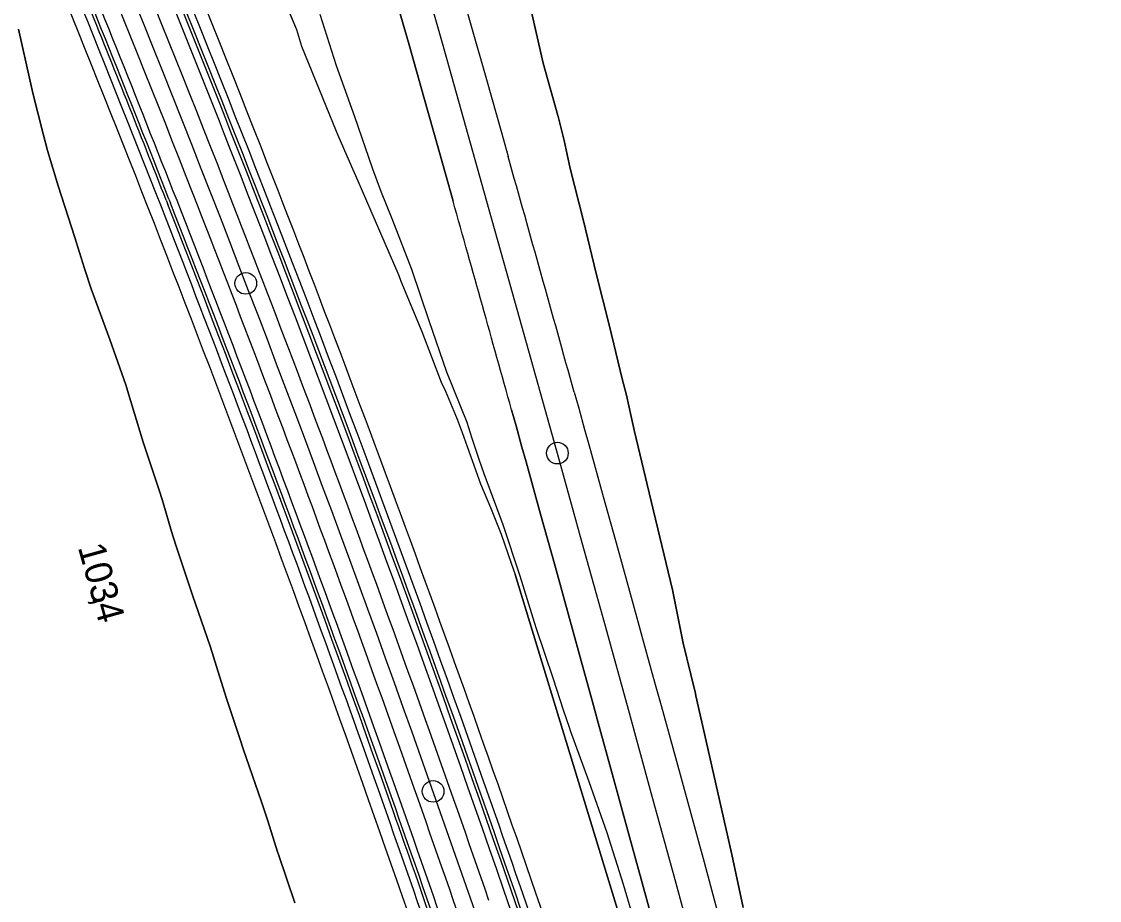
# Model space of a CAD drawing. Extents: x -678487 to -674601, y -1104811 to -1093295.
# Drawn here: x -676319.1 to -676120.1, y -1100094.2 to -1099931.9 of the extents above; entities that cross this region are included whole.
import ezdxf

# ---------------------------------------------------------------- set-up
doc = ezdxf.new("R2010")
doc.units = 0
for name, color, linetype in [('00_MiNGO', 7, 'Continuous'), ('SOxx02xx_Staničení_Popis', 7, 'Continuous'), ('SOxx02xx_ŽSp_hrana', 7, 'Continuous'), ('SOxx02xx_ŽSp_odvodnění', 7, 'Continuous'), ('SOxx02xx_ŽSp_zářez_hrana', 7, 'Continuous'), ('SOxx02xx_ŽSp_zářez_plocha', 7, 'Continuous'), ('SOxxxxxx_Osa_bod_P', 7, 'Continuous'), ('SOxxxxxx_Staničení_Popis', 7, 'Continuous'), ('SOxxxxxx_ŽSp_hrana', 7, 'Continuous'), ('SOxxxxxx_ŽSp_násyp_hrana', 7, 'Continuous'), ('SOxxxxxx_ŽSp_násyp_plocha', 7, 'Continuous')]:
    doc.layers.add(name, color=color, linetype=linetype)

msp = doc.modelspace()

# ---------------------------------------------------------------- linework, layer by layer
at = {"layer": '00_MiNGO'}
msp.add_line((-676192.76, -1100149.21), (-676227.95, -1100033.98), dxfattribs=at)
at = {"layer": 'SOxx02xx_Staničení_Popis'}
for centre in [(-676277.7, -1099980.23), (-676243.11, -1100074.06)]:
    msp.add_circle(centre, 2, dxfattribs=at)
at = {"layer": 'SOxx02xx_ŽSp_hrana'}
for centre, radius, start, end in [((-679543.77, -1101237.56), 3502.82, 21.366, 23.18091), ((-679544.28, -1101237.79), 3497.18, 21.36502, 23.18061), ((-679543.77, -1101237.56), 3502.82, 19.05102, 21.366), ((-679544.28, -1101237.79), 3497.18, 19.04918, 21.36502)]:
    msp.add_arc(centre, radius, start, end, dxfattribs=at)
at = {"layer": 'SOxx02xx_ŽSp_odvodnění'}
for p, q in [((-676292.41, -1099964.87), (-676292.11, -1099965.64)), ((-676291.9, -1099964.67), (-676291.6, -1099965.43))]:
    msp.add_line(p, q, dxfattribs=at)
for centre, radius, start, end in [((-679543.35, -1101237.38), 3507.42, 21.3668, 23.18116), ((-679543.4, -1101237.4), 3506.91, 21.36671, 22.7556), ((-679544.65, -1101237.95), 3493.09, 21.37783, 22.36101), ((-679544.7, -1101237.97), 3492.59, 21.37774, 22.02868), ((-679543.4, -1101237.4), 3506.92, 17.20156, 21.36671), ((-679543.35, -1101237.38), 3507.42, 18.2706, 21.3668), ((-679544.7, -1101237.97), 3492.59, 19.40341, 21.36421), ((-679544.65, -1101237.95), 3493.09, 19.04784, 21.3643), ((-679544.7, -1101237.97), 3492.59, 18.59256, 19.40341)]:
    msp.add_arc(centre, radius, start, end, dxfattribs=at)
at = {"layer": 'SOxx02xx_ŽSp_zářez_hrana'}
for p, q in [((-676271.23, -1099926.44), (-676268.36, -1099933.36)), ((-676319.71, -1099933.27), (-676317.54, -1099942.86)), ((-676268.36, -1099933.36), (-676267.4, -1099936.4)), ((-676267.4, -1099936.4), (-676264.86, -1099942.79)), ((-676317.54, -1099942.86), (-676316.95, -1099945.36)), ((-676264.86, -1099942.79), (-676261.03, -1099952.09)), ((-676316.95, -1099945.36), (-676315.12, -1099952.63)), ((-676261.03, -1099952.09), (-676260.71, -1099952.86)), ((-676315.12, -1099952.63), (-676314.3, -1099955.7)), ((-676260.71, -1099952.86), (-676258.64, -1099957.69)), ((-676314.3, -1099955.7), (-676312.33, -1099962.24)), ((-676258.64, -1099957.69), (-676256.99, -1099961.3)), ((-676256.99, -1099961.3), (-676252.99, -1099970.53)), ((-676312.33, -1099962.24), (-676309.28, -1099971.75)), ((-676309.28, -1099971.75), (-676309.03, -1099972.53)), ((-676252.99, -1099970.53), (-676249.42, -1099978.78)), ((-676309.03, -1099972.53), (-676307.47, -1099977.51)), ((-676307.47, -1099977.51), (-676306.26, -1099981.26)), ((-676249.42, -1099978.78), (-676249.09, -1099979.8)), ((-676249.09, -1099979.8), (-676245.22, -1099989.09)), ((-676306.26, -1099981.26), (-676302.83, -1099990.61)), ((-676245.22, -1099989.09), (-676241.62, -1099998.48)), ((-676302.83, -1099990.61), (-676299.88, -1099999)), ((-676299.88, -1099999), (-676299.83, -1099999.16)), ((-676299.83, -1099999.16), (-676299.55, -1100000.01)), ((-676299.55, -1100000.01), (-676296.69, -1100009.58)), ((-676241.62, -1099998.48), (-676240.85, -1100000.15)), ((-676240.85, -1100000.15), (-676238.69, -1100005.3)), ((-676238.69, -1100005.3), (-676237.73, -1100007.76)), ((-676237.73, -1100007.76), (-676234.34, -1100017.23)), ((-676296.69, -1100009.58), (-676293.49, -1100019.01)), ((-676234.34, -1100017.23), (-676232.52, -1100021.61)), ((-676293.49, -1100019.01), (-676292.97, -1100020.76)), ((-676292.97, -1100020.76), (-676291.43, -1100026.09)), ((-676232.52, -1100021.61), (-676230.57, -1100026.55)), ((-676291.43, -1100026.09), (-676290.65, -1100028.58)), ((-676230.57, -1100026.55), (-676228.69, -1100031.93)), ((-676290.65, -1100028.58), (-676287.49, -1100038.02)), ((-676228.69, -1100031.93), (-676227.95, -1100033.98)), ((-676287.49, -1100038.02), (-676285.94, -1100042.45)), ((-676285.94, -1100042.45), (-676284.25, -1100047.43)), ((-676284.25, -1100047.43), (-676282.56, -1100052.81)), ((-676282.56, -1100052.81), (-676281.25, -1100056.93)), ((-676281.25, -1100056.93), (-676278.89, -1100064.12)), ((-676278.89, -1100064.12), (-676278.13, -1100066.38)), ((-676278.13, -1100066.38), (-676274.88, -1100075.78)), ((-676274.88, -1100075.78), (-676273.64, -1100079.49)), ((-676273.64, -1100079.49), (-676271.83, -1100085.25)), ((-676271.83, -1100085.25), (-676271.68, -1100085.72)), ((-676271.68, -1100085.72), (-676268.64, -1100094.67))]:
    msp.add_line(p, q, dxfattribs=at)
for centre, radius, start, end in [((-679543.25, -1101237.33), 3508.58, 21.367, 23.18123), ((-679543.06, -1101237.24), 3510.69, 21.36737, 23.18134), ((-679544.8, -1101238.02), 3491.42, 21.36401, 22.85251), ((-679543.5, -1101237.44), 3505.75, 21.36651, 22.7555), ((-679544.54, -1101237.91), 3494.25, 21.36451, 22.36114), ((-679544.99, -1101238.11), 3489.31, 19.0466, 22.3606), ((-679543.06, -1101237.24), 3510.69, 18.59094, 21.36737), ((-679543.5, -1101237.44), 3505.75, 17.15913, 21.36651), ((-679543.25, -1101237.33), 3508.58, 19.41645, 21.367), ((-679544.8, -1101238.02), 3491.42, 19.04729, 21.36401), ((-679544.54, -1101237.91), 3494.25, 19.04822, 21.36451), ((-679543.25, -1101237.33), 3508.58, 19.03362, 19.41645), ((-679543.25, -1101237.33), 3508.58, 17.16041, 19.03362)]:
    msp.add_arc(centre, radius, start, end, dxfattribs=at)
at = {"layer": 'SOxx02xx_ŽSp_zářez_plocha'}
msp.add_line((-676227.95, -1100033.98), (-676192.76, -1100149.21), dxfattribs=at)
for points in [[(-676271.23, -1099926.44), (-676268.36, -1099933.36), (-676267.4, -1099936.4), (-676264.86, -1099942.79), (-676261.03, -1099952.09), (-676260.71, -1099952.86), (-676258.64, -1099957.69), (-676256.99, -1099961.3), (-676252.99, -1099970.53), (-676249.42, -1099978.78), (-676249.09, -1099979.8), (-676245.22, -1099989.09), (-676241.62, -1099998.48), (-676240.85, -1100000.15), (-676238.69, -1100005.3), (-676237.73, -1100007.76), (-676234.34, -1100017.23), (-676232.52, -1100021.61), (-676230.57, -1100026.55), (-676228.69, -1100031.93), (-676227.95, -1100033.98)], [(-676268.64, -1100094.67), (-676271.68, -1100085.72), (-676271.83, -1100085.25), (-676273.64, -1100079.49), (-676274.88, -1100075.78), (-676278.13, -1100066.38), (-676278.89, -1100064.12), (-676281.25, -1100056.93), (-676282.56, -1100052.81), (-676284.25, -1100047.43), (-676285.94, -1100042.45), (-676287.49, -1100038.02), (-676290.65, -1100028.58), (-676291.43, -1100026.09), (-676292.97, -1100020.76), (-676293.49, -1100019.01), (-676296.69, -1100009.58), (-676299.55, -1100000.01), (-676299.83, -1099999.16), (-676299.88, -1099999), (-676302.83, -1099990.61), (-676306.26, -1099981.26), (-676307.47, -1099977.51), (-676309.03, -1099972.53), (-676309.28, -1099971.75), (-676312.33, -1099962.24), (-676314.3, -1099955.7), (-676315.12, -1099952.63), (-676316.95, -1099945.36), (-676317.54, -1099942.86), (-676319.71, -1099933.27)]]:
    msp.add_lwpolyline(points, dxfattribs=at)
for centre, radius, start, end in [((-679543.06, -1101237.24), 3510.69, 21.36737, 23.18134), ((-679544.99, -1101238.11), 3489.31, 19.0466, 22.3606), ((-679543.06, -1101237.24), 3510.69, 18.59094, 21.36737)]:
    msp.add_arc(centre, radius, start, end, dxfattribs=at)
at = {"layer": 'SOxxxxxx_Osa_bod_P'}
for centre, radius, start, end in [((-693563.22, -1104838.51), 18002.25, 14.227837, 20.731742), ((-679544.02, -1101237.67), 3500, 17.15654, 27.27761)]:
    msp.add_arc(centre, radius, start, end, dxfattribs=at)
at = {"layer": 'SOxxxxxx_Staničení_Popis'}
for p, q in [((-676277.7, -1099980.23), (-676277.7, -1099980.23)), ((-676220.16, -1100011.59), (-676220.16, -1100011.59)), ((-676243.11, -1100074.06), (-676243.11, -1100074.06))]:
    msp.add_line(p, q, dxfattribs=at)
for centre in [(-676277.7, -1099980.23), (-676220.16, -1100011.59), (-676243.11, -1100074.06)]:
    msp.add_circle(centre, 2, dxfattribs=at)
at = {"layer": 'SOxxxxxx_ŽSp_hrana'}
for points in [[(-676289.01, -1099792.09), (-676286.21, -1099801.69), (-676285.8, -1099803.08), (-676284.09, -1099808.96), (-676283.41, -1099811.29), (-676280.62, -1099820.89), (-676277.84, -1099830.49), (-676275.06, -1099840.09), (-676272.29, -1099849.7), (-676271.08, -1099853.88), (-676269.52, -1099859.3), (-676266.75, -1099868.91), (-676264, -1099878.52), (-676261.24, -1099888.13), (-676258.5, -1099897.74), (-676256.5, -1099904.73), (-676255.11, -1099909.63), (-676253.02, -1099916.97), (-676250.29, -1099926.58), (-676247.56, -1099936.2), (-676244.84, -1099945.82), (-676242.08, -1099955.61), (-676240.83, -1099960.03), (-676239.42, -1099965.06)], [(-676238.72, -1099923.3), (-676236, -1099932.93), (-676233.27, -1099942.55), (-676230.51, -1099952.35), (-676229.26, -1099956.77)], [(-676217.05, -1100000.34), (-676216.22, -1100003.31), (-676215.13, -1100007.25), (-676214.37, -1100009.98), (-676211.69, -1100019.61), (-676209.01, -1100029.25), (-676206.34, -1100038.89), (-676203.68, -1100048.54), (-676202.09, -1100054.31), (-676201.02, -1100058.18), (-676198.37, -1100067.82), (-676195.72, -1100077.47), (-676193.08, -1100087.12), (-676190.44, -1100096.77), (-676188.1, -1100105.36), (-676187.3, -1100108.32), (-676185.19, -1100116.07)], [(-676228.63, -1100003.57), (-676227.8, -1100006.54), (-676226.71, -1100010.47), (-676225.95, -1100013.2), (-676223.27, -1100022.83), (-676220.6, -1100032.46), (-676217.93, -1100042.1), (-676215.27, -1100051.73), (-676213.68, -1100057.51), (-676212.61, -1100061.37), (-676209.96, -1100071.01), (-676207.32, -1100080.65), (-676204.68, -1100090.29), (-676202.04, -1100099.93)]]:
    msp.add_lwpolyline(points, dxfattribs=at)
for radius, end in [(18008.26, 15.728738), (17996.24, 15.712091)]:
    msp.add_arc((-693563.22, -1104838.51), radius, 15.584783, end, dxfattribs=at)
at = {"layer": 'SOxxxxxx_ŽSp_násyp_hrana'}
for p, q in [((-676225, -1099929.82), (-676222.8, -1099939.59)), ((-676264.01, -1099930.48), (-676260.99, -1099940)), ((-676260.99, -1099940), (-676257.66, -1099949.44)), ((-676222.8, -1099939.59), (-676220.07, -1099949.22)), ((-676257.66, -1099949.44), (-676254.37, -1099958.89)), ((-676220.07, -1099949.22), (-676220.03, -1099949.39)), ((-676220.03, -1099949.39), (-676218.9, -1099953.85)), ((-676218.9, -1099953.85), (-676217.83, -1099958.99)), ((-676254.37, -1099958.89), (-676254.31, -1099959.06)), ((-676254.31, -1099959.06), (-676252.68, -1099963.37)), ((-676217.83, -1099958.99), (-676215.31, -1099968.68)), ((-676252.68, -1099963.37), (-676250.76, -1099968.25)), ((-676250.76, -1099968.25), (-676247.13, -1099977.61)), ((-676215.31, -1099968.68), (-676212.97, -1099978.42)), ((-676247.13, -1099977.61), (-676243.92, -1099987.09)), ((-676212.97, -1099978.42), (-676210.51, -1099988.12)), ((-676243.92, -1099987.09), (-676240.64, -1099996.55)), ((-676210.51, -1099988.12), (-676208.18, -1099997.87)), ((-676240.64, -1099996.55), (-676236.91, -1100005.88)), ((-676208.18, -1099997.87), (-676207.41, -1100000.85)), ((-676207.41, -1100000.85), (-676206.51, -1100004.85)), ((-676236.91, -1100005.88), (-676235.95, -1100008.81)), ((-676206.51, -1100004.85), (-676205.91, -1100007.62)), ((-676205.91, -1100007.62), (-676203.56, -1100017.36)), ((-676235.95, -1100008.81), (-676234.65, -1100012.68)), ((-676234.65, -1100012.68), (-676233.73, -1100015.37)), ((-676233.73, -1100015.37), (-676230.23, -1100024.76)), ((-676203.56, -1100017.36), (-676201.23, -1100027.09)), ((-676230.23, -1100024.76), (-676227.08, -1100034.26)), ((-676201.23, -1100027.09), (-676198.87, -1100036.83)), ((-676227.08, -1100034.26), (-676224.16, -1100043.82)), ((-676198.87, -1100036.83), (-676196.93, -1100046.67)), ((-676224.16, -1100043.82), (-676220.91, -1100053.29)), ((-676196.93, -1100046.67), (-676195.5, -1100052.5)), ((-676220.91, -1100053.29), (-676219.08, -1100059)), ((-676195.5, -1100052.5), (-676194.67, -1100055.98)), ((-676194.67, -1100055.98), (-676194.58, -1100056.41)), ((-676194.58, -1100056.41), (-676192.36, -1100066.17)), ((-676219.08, -1100059), (-676217.95, -1100062.39)), ((-676217.95, -1100062.39), (-676217.81, -1100062.8)), ((-676217.81, -1100062.8), (-676214.35, -1100072.22)), ((-676192.36, -1100066.17), (-676190.14, -1100075.94)), ((-676214.35, -1100072.22), (-676211.03, -1100081.67)), ((-676190.14, -1100075.94), (-676187.95, -1100085.72)), ((-676211.03, -1100081.67), (-676208.02, -1100091.21)), ((-676187.95, -1100085.72), (-676185.84, -1100095.51)), ((-676208.02, -1100091.21), (-676205.17, -1100100.79))]:
    msp.add_line(p, q, dxfattribs=at)
at = {"layer": 'SOxxxxxx_ŽSp_násyp_plocha'}
for points in [[(-676239.42, -1099965.06), (-676240.83, -1099960.03), (-676242.08, -1099955.61), (-676244.84, -1099945.82), (-676247.56, -1099936.2), (-676250.29, -1099926.58), (-676253.02, -1099916.97), (-676255.11, -1099909.63), (-676256.5, -1099904.73), (-676258.5, -1099897.74), (-676261.24, -1099888.13), (-676264, -1099878.52), (-676266.75, -1099868.91), (-676269.52, -1099859.3), (-676271.08, -1099853.88), (-676272.29, -1099849.7), (-676275.06, -1099840.09), (-676277.84, -1099830.49), (-676280.62, -1099820.89), (-676283.41, -1099811.29), (-676284.09, -1099808.96), (-676285.8, -1099803.08), (-676286.21, -1099801.69), (-676289.01, -1099792.09)], [(-676238.72, -1099923.3), (-676236, -1099932.93), (-676233.27, -1099942.55), (-676230.51, -1099952.35), (-676229.26, -1099956.77)], [(-676185.84, -1100095.51), (-676187.95, -1100085.72), (-676190.14, -1100075.94), (-676192.36, -1100066.17), (-676194.58, -1100056.41), (-676194.67, -1100055.98), (-676195.5, -1100052.5), (-676196.93, -1100046.67), (-676198.87, -1100036.83), (-676201.23, -1100027.09), (-676203.56, -1100017.36), (-676205.91, -1100007.62), (-676206.51, -1100004.85), (-676207.41, -1100000.85), (-676208.18, -1099997.87), (-676210.51, -1099988.12), (-676212.97, -1099978.42), (-676215.31, -1099968.68), (-676217.83, -1099958.99), (-676218.9, -1099953.85), (-676220.03, -1099949.39), (-676220.07, -1099949.22), (-676222.8, -1099939.59), (-676225, -1099929.82)], [(-676264.01, -1099930.48), (-676260.99, -1099940), (-676257.66, -1099949.44), (-676254.37, -1099958.89), (-676254.31, -1099959.06), (-676252.68, -1099963.37), (-676250.76, -1099968.25), (-676247.13, -1099977.61), (-676243.92, -1099987.09), (-676240.64, -1099996.55), (-676236.91, -1100005.88), (-676235.95, -1100008.81), (-676234.65, -1100012.68), (-676233.73, -1100015.37), (-676230.23, -1100024.76), (-676227.08, -1100034.26), (-676224.16, -1100043.82), (-676220.91, -1100053.29), (-676219.08, -1100059), (-676217.95, -1100062.39), (-676217.81, -1100062.8), (-676214.35, -1100072.22), (-676211.03, -1100081.67), (-676208.02, -1100091.21), (-676205.17, -1100100.79)], [(-676217.05, -1100000.34), (-676216.22, -1100003.31), (-676215.13, -1100007.25), (-676214.37, -1100009.98), (-676211.69, -1100019.61), (-676209.01, -1100029.25), (-676206.34, -1100038.89), (-676203.68, -1100048.54), (-676202.09, -1100054.31), (-676201.02, -1100058.18), (-676198.37, -1100067.82), (-676195.72, -1100077.47), (-676193.08, -1100087.12), (-676190.44, -1100096.77), (-676188.1, -1100105.36), (-676187.3, -1100108.32), (-676185.19, -1100116.07)], [(-676184.46, -1100164.83), (-676185.21, -1100162.03), (-676186.34, -1100157.82), (-676188.95, -1100148.17), (-676191.55, -1100138.52), (-676194.17, -1100128.87), (-676196.79, -1100119.22), (-676198.9, -1100111.47), (-676199.7, -1100108.52), (-676202.04, -1100099.93), (-676204.68, -1100090.29), (-676207.32, -1100080.65), (-676209.96, -1100071.01), (-676212.61, -1100061.37), (-676213.68, -1100057.51), (-676215.27, -1100051.73), (-676217.93, -1100042.1), (-676220.6, -1100032.46), (-676223.27, -1100022.83), (-676225.95, -1100013.2), (-676226.71, -1100010.47), (-676227.8, -1100006.54), (-676228.63, -1100003.57)]]:
    msp.add_lwpolyline(points, dxfattribs=at)
for radius, end in [(18008.26, 15.728738), (17996.24, 15.712091)]:
    msp.add_arc((-693563.22, -1104838.51), radius, 15.584783, end, dxfattribs=at)

# ---------------------------------------------------------------- texts
at = {"layer": 'SOxxxxxx_Staničení_Popis'}
for s, p in [('103', (-676308.75, -1100028.95)), (',', (-676306.18, -1100038.16)), ('4', (-676305.76, -1100039.69))]:
    msp.add_text(s, height=5, rotation=285.553, dxfattribs=at).set_placement(p)

doc.saveas('drawing.dxf')
